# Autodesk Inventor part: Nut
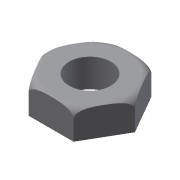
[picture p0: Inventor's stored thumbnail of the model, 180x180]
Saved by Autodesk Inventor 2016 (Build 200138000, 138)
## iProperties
Created: 2009-04
Part Number: Nut
Document SubType Name: Modeling
Designer: Sham
Density: 1 g/cm^3
Material: Generic
Appearance: Default
Author: Sham
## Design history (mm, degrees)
sketch "Sketch1"
  geometry: L1 (19.919, 34.5)-(39.837, 0); L2 (39.837, 0)-(19.919, -34.5); L3 (19.919, -34.5)-(-19.919, -34.5); L4 (-19.919, -34.5)-(-39.837, 0); L5 (-39.837, 0)-(-19.919, 34.5); L6 (-19.919, 34.5)-(19.919, 34.5); C1 r 18.5 at (0, 0); 1 further point
  constraints: 12 end point, 1 centre point, 1 coincident, 13 other
  dimensions: "d0" = 69 distance between parallel lines of L3 L6; "d1" = 37 diameter of C1
extrude "Extrusion1" new body sketch "Sketch1" distance "d2" = 25; taper "d3" = 0 deg
sketch "Sketch2"
  geometry: L1 (0, -5.4)-(0, 32.4) reference; L2 (-19.919, 25)-(-39.837, 25) reference; L3 (-19.919, 25)-(-39.837, 25) reference; L4 (-39.837, 0)-(-39.837, 25) reference; L5 (-19.919, 0)-(-39.837, 0) reference; L6 (-19.919, 0)-(-19.919, 25) reference; A1 r 7.5 centre (-32.337, 17.5) between (-32.337, 25) and (-39.837, 17.5); 1 further point
  constraints: 2 midpoint, 2 point on circle, 2 point on line, 2 tangent, 1 centre point
  dimensions: "d6" = 7.5 radius of A1
revolve "Revolution1" sketch "Sketch2" stored, may be unused: angle "d5" = 90 deg
body "Solid1"
node "Projected Loop1"
other parameters: "d4" = 90 deg
